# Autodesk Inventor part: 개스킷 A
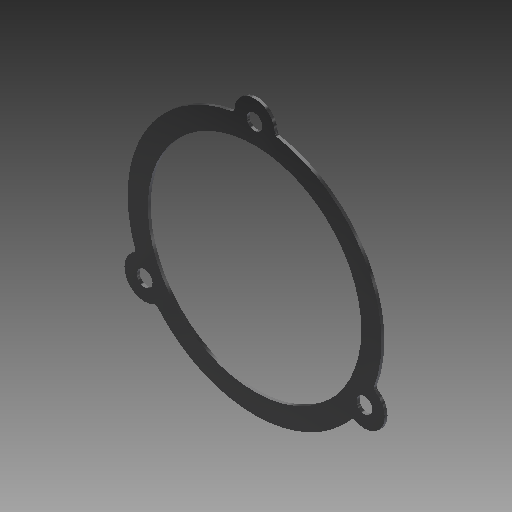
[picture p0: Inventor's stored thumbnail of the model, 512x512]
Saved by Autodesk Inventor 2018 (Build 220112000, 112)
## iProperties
Created: 2020-03
Part Number: 개스킷 A
Material: 고무
Document SubType Name: Modeling
Designer: mduedu
Density: 1 g/cm^3
Appearance: 고무 - 검은색 - 버전 1.1
Author: mduedu
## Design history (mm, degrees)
sketch "스케치1" dims "d1" = 88
  geometry: C1 r 37 at (0, 0); C2 r 7 at (0, 44); C3 r 7 at (-38.105, -22); C4 r 7 at (38.105, -22); 2 further points
  constraints: 4 centre point, 2 coincident, 2 vertical alignment, 9 other
  dimensions: "d0" = 74 diameter of C1; "d2" = 14 diameter of C2; "d5" = 360 deg dimension on point (0, 0) C2.centre (derived)
extrude "돌출1" new body sketch "스케치1" distance "d7" = 1; taper "d8" = 0 deg
fillet "모깎기1" dims "d9" = 1
sketch "스케치2"
  geometry: C1 r 37 at (0, 0) reference; A1 r 44 centre (0, 0) between (-7.817, 43.3) and (-41.408, -14.88) reference; A2 r 1 centre (-42.349, -15.218) between (-41.818, -16.066) and (-41.408, -14.88) reference; A3 r 7 centre (-38.105, -22) between (-41.818, -16.066) and (-34.823, -28.183) reference; A4 r 1 centre (-34.354, -29.066) between (-33.59, -28.42) and (-34.823, -28.183) reference; A5 r 44 centre (0, 0) between (-33.59, -28.42) and (33.59, -28.42) reference; A6 r 1 centre (34.354, -29.066) between (34.823, -28.183) and (33.59, -28.42) reference; A7 r 7 centre (38.105, -22) between (34.823, -28.183) and (41.818, -16.066) reference; A8 r 1 centre (42.349, -15.218) between (41.408, -14.88) and (41.818, -16.066) reference; A9 r 44 centre (0, 0) between (41.408, -14.88) and (7.817, 43.3) reference; A10 r 1 centre (7.995, 44.284) between (6.996, 44.249) and (7.817, 43.3) reference; A11 r 7 centre (0, 44) between (6.996, 44.249) and (-6.996, 44.249) reference; A12 r 1 centre (-7.995, 44.284) between (-7.817, 43.3) and (-6.996, 44.249) reference; 4 further points
  constraints: 3 coincident
hole "구멍1" sketch "스케치2" at (0, 44), (-38.105, -22), (38.105, -22) diameter "d10" = 5.5; stored, may be unused: countersink angle "d14" = 90 deg, drill point angle "d16" = 118 deg; dims "d11" = 6, "d12" = 10, "d13" = 5.7, "d15" = 8
node "솔리드1"
node "투영된 루프1"
